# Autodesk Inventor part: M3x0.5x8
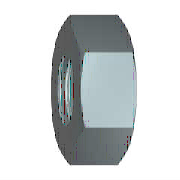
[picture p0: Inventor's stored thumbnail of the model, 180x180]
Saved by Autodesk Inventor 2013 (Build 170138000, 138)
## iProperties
Created: 2009-02
Part Number: M3x0.5x8
Material: 강, 연강
Description: 6각 너트 및 6각 가는 너트
Document SubType Name: Modeling
Standard: KS B 1012
Designer: KYOUNG IL JANG
Standards Organization: KS
Language: ko-KR
Size Designation: C M8
Categories: <MemberInstance><Categories><Category DisplayName="조임쇠" InternalName="e4da775c-781d-43d5-af7c-5136215cf5a6" Mnemonic="FSTN"><Category DisplayName="너트" InternalN
Density: 1 g/cm^3
Vendor: CBT Solutions
Company: 한국ATC센터
IsCustomPart: 0
Author: KYOUNG IL JANG
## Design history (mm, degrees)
sketch "스케치1"
  geometry: L1 (-7.506, 0)-(-3.753, 6.5); L2 (-3.753, 6.5)-(3.753, 6.5); L3 (3.753, 6.5)-(7.506, 0); L4 (7.506, 0)-(3.753, -6.5); L5 (3.753, -6.5)-(-3.753, -6.5); L6 (-3.753, -6.5)-(-7.506, 0); 2 further points
  constraints: 12 end point, 1 coincident, 1 horizontal, 11 other
  dimensions: "d0" = 15.01111 distance of L3.end L1.start (= 1.1547 x SW)
extrude "본체" new body sketch "스케치1" distance "d1" = 7.9 (= KOH); taper "d2" = 0 deg
sketch "스케치2"
  geometry: L1 (0, 3.753)-(0, 7.506) reference; L2 (0, 7.506)-(7.9, 7.506) reference; L3 (7.9, 3.753)-(7.9, 7.506) reference; L4 (-1.58, 0)-(9.48, 0) reference; L5 (0.581, 7.506)-(0, 6.5); L6 (7.319, 7.506)-(7.9, 6.5)
  constraints: 4 end point, 4 point on line
  dimensions: "d3" = 30 deg angle of L1 L5 (= ANG1); "d4" = 30 deg angle of L3 L6 (= ANG2); "d5" = 13 diameter of L5.end L4 (= SW0); "d6" = 13 diameter of L6.end L4 (= SW01)
revolve "모따기1" sketch "스케치2" stored, may be unused: angle "d7" = 90 deg
sketch "스케치3"
  geometry: A1 r 6.5 centre (0, 0) between (-3.25, -5.629) and (3.25, -5.629) reference; 1 further point
  constraints: 1 coincident
hole "스레드" sketch "스케치3" at (0, 0) diameter "d25" = 6.647; stored, may be unused: countersink angle "d29" = 82 deg, drill point angle "d31" = 118 deg; dims "d26" = 6, "d27" = 4, "d28" = 2, "d30" = 8
workaxis "Work Axis1"
workplane "Work Plane1"
body "Solid1"
chamfer "모따기2" distance "d8" = 0.67658 (= -0.5 x GD1 + 0.5 x NND); stored, may be unused: angle "d9" = 30 deg, second distance "d40" = 0.67658 (= -0.5 x GD1 + 0.5 x NND)
chamfer "모따기3" distance "d10" = 0.67658 (= -0.5 x GD1 + 0.5 x NND); stored, may be unused: angle "d11" = 30 deg, second distance "d41" = 0.67658 (= -0.5 x GD1 + 0.5 x NND)
other parameters: "ANG1" = 30 deg [user parameter; used in 1 equation term], "ANG2" = 30 deg [user parameter; used in 1 equation term], "NND" = 8 [user parameter; used in 4 equation terms], "KOH" = 7.9 [user parameter; used in 1 equation term], "SW" = 13 [user parameter; used in 4 equation terms], "SW0" = 13 (= SW) [user parameter; used in 1 equation term], "SW01" = 13 (= SW) [user parameter; used in 1 equation term], "GD1" = 6.64684 (computed from THREADDIA, PTC, TOA) [user parameter; used in 4 equation terms], "d13" = 0, "d14" = 0, "d39" = 0, "d42" = 0, "GUL" = 0.67658 (= 0.541266 x PTC) [user parameter], "TPU" = 8 (computed from PTC) [user parameter], "THREADDIA" = 8 [user parameter; used in 1 equation term], "TOA" = 30 deg [user parameter; used in 1 equation term], "PTC" = 1.25 [user parameter; used in 4 equation terms], "E0" = 15.015 (= 1.155 x SW) [user parameter], "GAL" = 0.67658 (= 0.541266 x PTC) [user parameter]
